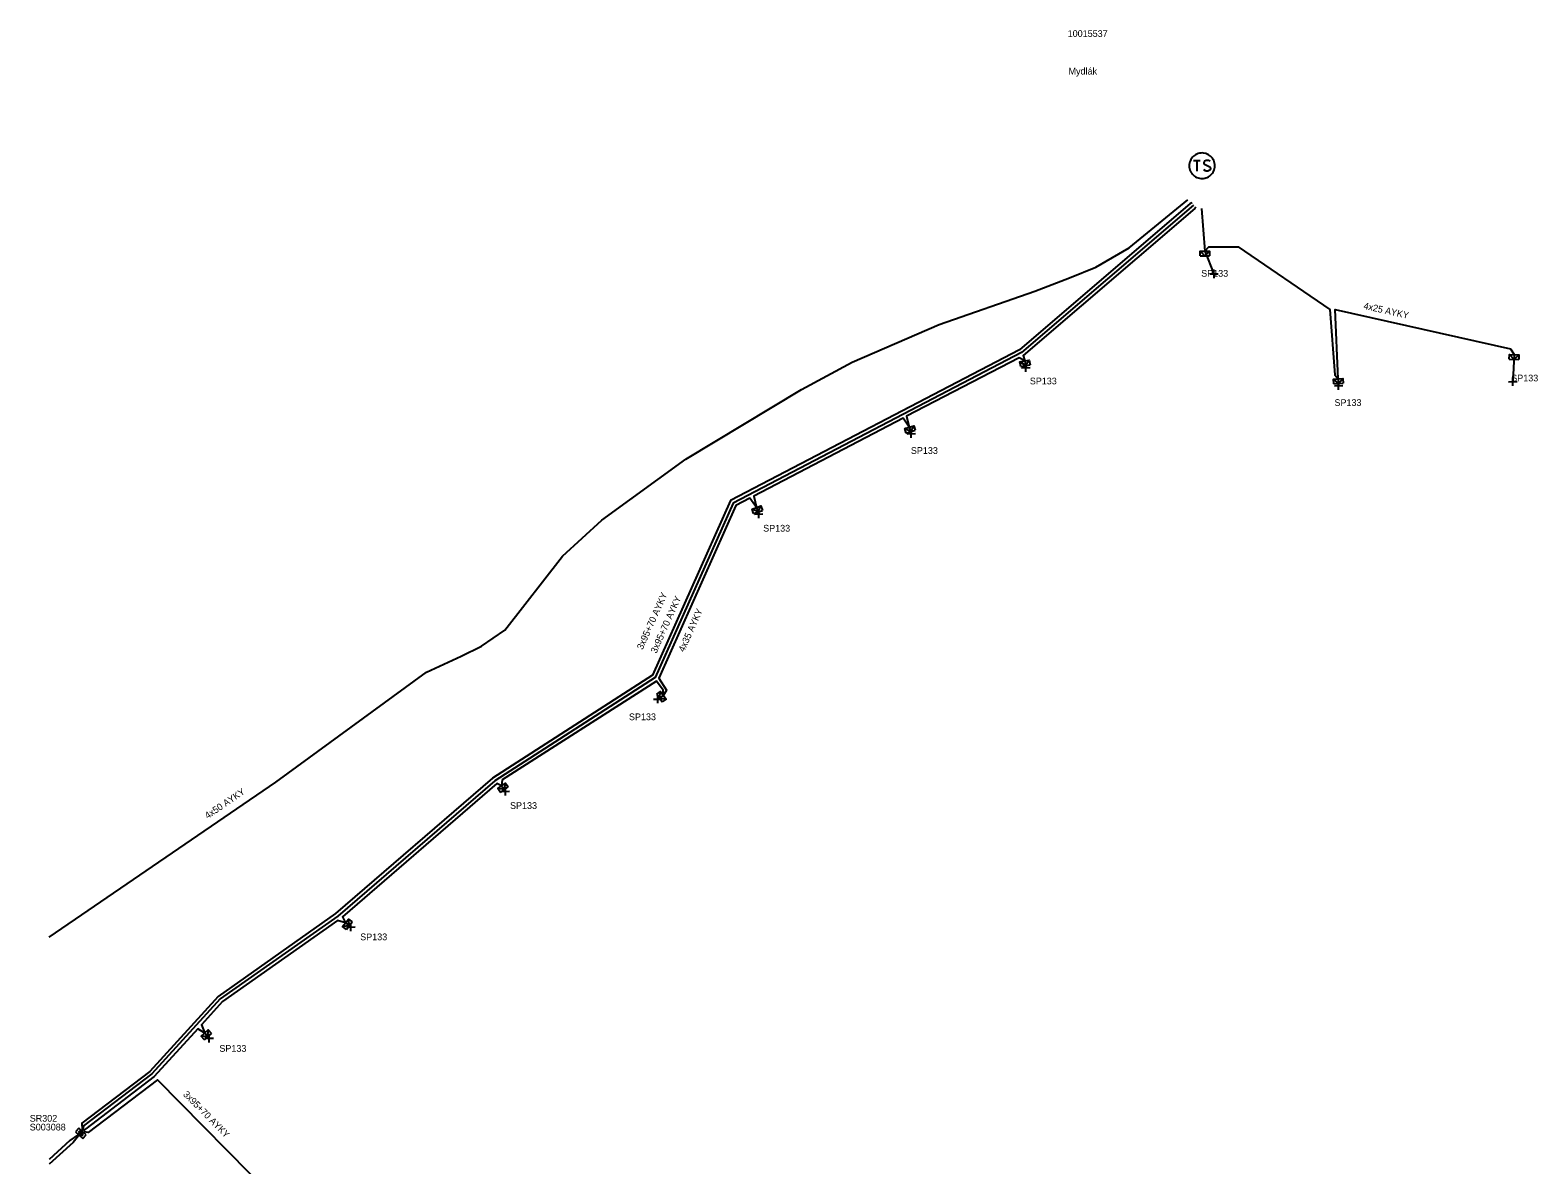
# Model space of a CAD drawing. Extents: x -762503 to -762212, y -1153994 to -1153331.
# Drawn here: x -762502.8 to -762279.8, y -1153498.9 to -1153331.1 of the extents above; entities that cross this region are included whole.
import ezdxf

# ---------------------------------------------------------------- set-up
doc = ezdxf.new("R2010")
doc.units = 0
for name, color, linetype in [('Vrstva 25', 7, 'Continuous'), ('Vrstva 26', 7, 'Continuous'), ('Vrstva 27', 7, 'Continuous'), ('Vrstva 28', 7, 'Continuous'), ('Vrstva 29', 7, 'Continuous'), ('Vrstva 30', 7, 'Continuous'), ('Vrstva 31', 7, 'Continuous'), ('Vrstva 33', 7, 'Continuous'), ('Vrstva 34', 7, 'Continuous'), ('Vrstva 5', 7, 'Continuous'), ('Vrstva 59', 7, 'Continuous'), ('Vrstva 6', 7, 'Continuous')]:
    doc.layers.add(name, color=color, linetype=linetype)

msp = doc.modelspace()

# ---------------------------------------------------------------- linework, layer by layer
at = {"layer": 'Vrstva 25'}
for points in [[(-762327.567, -1153351.151), (-762327.578, -1153350.954), (-762327.609, -1153350.758), (-762327.66, -1153350.567), (-762327.732, -1153350.382), (-762327.821, -1153350.207), (-762327.929, -1153350.041), (-762328.053, -1153349.887), (-762328.193, -1153349.747), (-762328.347, -1153349.623), (-762328.513, -1153349.515), (-762328.689, -1153349.425), (-762328.873, -1153349.354), (-762329.26, -1153349.272), (-762329.26, -1153349.272), (-762329.457, -1153349.261), (-762329.655, -1153349.272), (-762329.851, -1153349.303), (-762330.041, -1153349.354), (-762330.227, -1153349.425), (-762330.402, -1153349.515), (-762330.568, -1153349.623), (-762330.722, -1153349.747), (-762330.862, -1153349.887), (-762330.986, -1153350.041), (-762331.094, -1153350.207), (-762331.184, -1153350.382), (-762331.255, -1153350.567), (-762331.306, -1153350.758), (-762331.337, -1153350.954), (-762331.348, -1153351.151), (-762331.337, -1153351.349), (-762331.306, -1153351.545), (-762331.255, -1153351.735), (-762331.184, -1153351.92), (-762331.094, -1153352.096), (-762330.986, -1153352.262), (-762330.861, -1153352.416), (-762330.722, -1153352.555), (-762330.568, -1153352.68), (-762330.402, -1153352.788), (-762330.226, -1153352.878), (-762330.041, -1153352.949), (-762329.851, -1153353), (-762329.655, -1153353.031), (-762329.457, -1153353.042), (-762329.26, -1153353.031), (-762329.065, -1153353), (-762328.873, -1153352.949), (-762328.689, -1153352.878), (-762328.513, -1153352.788), (-762328.347, -1153352.68), (-762328.193, -1153352.555), (-762328.053, -1153352.416), (-762327.929, -1153352.262), (-762327.821, -1153352.096), (-762327.732, -1153351.92), (-762327.66, -1153351.735), (-762327.609, -1153351.545), (-762327.578, -1153351.349), (-762327.567, -1153351.151)], [(-762330.719, -1153350.368), (-762329.711, -1153350.368)], [(-762330.215, -1153350.368), (-762330.215, -1153351.942)], [(-762328.262, -1153350.494), (-762328.514, -1153350.368), (-762328.829, -1153350.368), (-762329.081, -1153350.494), (-762329.207, -1153350.682), (-762329.207, -1153350.746), (-762329.081, -1153350.934), (-762328.325, -1153351.312), (-762328.199, -1153351.47), (-762328.199, -1153351.628), (-762328.325, -1153351.816), (-762328.577, -1153351.942), (-762328.829, -1153351.942), (-762328.955, -1153351.88), (-762329.207, -1153351.754)]]:
    msp.add_lwpolyline(points, dxfattribs=at)
at = {"layer": 'Vrstva 28'}
for points in [[(-762495.603, -1153493.457), (-762496.105, -1153494.014)], [(-762496.105, -1153494.014), (-762494.991, -1153495.018)], [(-762495.449, -1153493.842), (-762495.702, -1153494.123)], [(-762495.702, -1153494.123), (-762495.149, -1153494.621)], [(-762495.446, -1153493.909), (-762495.636, -1153494.119)], [(-762495.636, -1153494.119), (-762495.153, -1153494.554)], [(-762494.489, -1153494.461), (-762495.603, -1153493.457)], [(-762495.442, -1153493.976), (-762495.569, -1153494.116)], [(-762495.569, -1153494.116), (-762495.156, -1153494.487)], [(-762495.439, -1153494.042), (-762495.502, -1153494.112)], [(-762495.502, -1153494.112), (-762495.16, -1153494.421)], [(-762494.896, -1153494.34), (-762495.449, -1153493.842)], [(-762494.963, -1153494.344), (-762495.446, -1153493.909)], [(-762495.03, -1153494.347), (-762495.442, -1153493.976)], [(-762495.44, -1153494.105), (-762495.159, -1153494.358)], [(-762495.097, -1153494.351), (-762495.439, -1153494.042)], [(-762495.16, -1153494.421), (-762495.097, -1153494.351)], [(-762495.156, -1153494.487), (-762495.03, -1153494.347)], [(-762495.153, -1153494.554), (-762494.963, -1153494.344)], [(-762495.149, -1153494.621), (-762494.896, -1153494.34)], [(-762494.991, -1153495.018), (-762494.489, -1153494.461)]]:
    msp.add_lwpolyline(points, dxfattribs=at)
at = {"layer": 'Vrstva 31'}
for points in [[(-762329.053, -1153364.48), (-762329.753, -1153363.78)], [(-762329.753, -1153364.48), (-762329.753, -1153363.78), (-762328.353, -1153363.78), (-762328.353, -1153364.48)], [(-762329.753, -1153364.48), (-762328.353, -1153364.48)], [(-762329.053, -1153364.48), (-762328.353, -1153363.78)], [(-762284.006, -1153379.755), (-762283.982, -1153379.056), (-762282.583, -1153379.105), (-762282.607, -1153379.804)], [(-762283.307, -1153379.78), (-762283.982, -1153379.056)], [(-762283.307, -1153379.78), (-762282.583, -1153379.105)], [(-762356.261, -1153380.821), (-762356.382, -1153380.132), (-762355.004, -1153379.889), (-762354.882, -1153380.578)], [(-762355.571, -1153380.7), (-762356.382, -1153380.132)], [(-762356.261, -1153380.821), (-762354.882, -1153380.578)], [(-762355.571, -1153380.7), (-762355.004, -1153379.889)], [(-762284.006, -1153379.755), (-762282.607, -1153379.804)], [(-762309.983, -1153383.418), (-762310.032, -1153382.719), (-762308.635, -1153382.622), (-762308.586, -1153383.32)], [(-762309.285, -1153383.369), (-762310.032, -1153382.719)], [(-762309.983, -1153383.418), (-762308.586, -1153383.32)], [(-762309.285, -1153383.369), (-762308.635, -1153382.622)], [(-762373.217, -1153390.685), (-762373.422, -1153390.016), (-762372.083, -1153389.607), (-762371.879, -1153390.276)], [(-762372.548, -1153390.481), (-762373.422, -1153390.016)], [(-762373.217, -1153390.685), (-762371.879, -1153390.276)], [(-762372.548, -1153390.481), (-762372.083, -1153389.607)], [(-762395.787, -1153402.581), (-762396.015, -1153401.92), (-762394.691, -1153401.464), (-762394.463, -1153402.126)], [(-762395.125, -1153402.354), (-762394.691, -1153401.464)], [(-762395.125, -1153402.354), (-762396.015, -1153401.92)], [(-762395.787, -1153402.581), (-762394.463, -1153402.126)], [(-762410.107, -1153429.276), (-762409.534, -1153428.874), (-762408.731, -1153430.021), (-762409.304, -1153430.422)], [(-762410.107, -1153429.276), (-762409.304, -1153430.422)], [(-762409.706, -1153429.849), (-762409.534, -1153428.874)], [(-762409.706, -1153429.849), (-762408.731, -1153430.021)], [(-762433.224, -1153443.817), (-762433.626, -1153443.244), (-762432.479, -1153442.441), (-762432.077, -1153443.014)], [(-762432.651, -1153443.415), (-762433.626, -1153443.244)], [(-762433.224, -1153443.817), (-762432.077, -1153443.014)], [(-762432.651, -1153443.415), (-762432.479, -1153442.441)], [(-762456.021, -1153464.085), (-762456.572, -1153463.654), (-762455.71, -1153462.551), (-762455.159, -1153462.982)], [(-762455.59, -1153463.533), (-762456.572, -1153463.654)], [(-762456.021, -1153464.085), (-762455.159, -1153462.982)], [(-762455.59, -1153463.533), (-762455.71, -1153462.551)], [(-762477.024, -1153480.411), (-762477.492, -1153479.89), (-762476.452, -1153478.954), (-762475.983, -1153479.474)], [(-762477.024, -1153480.411), (-762475.983, -1153479.474)], [(-762476.504, -1153479.942), (-762476.452, -1153478.954)], [(-762476.504, -1153479.942), (-762477.492, -1153479.89)]]:
    msp.add_lwpolyline(points, dxfattribs=at)
at = {"layer": 'Vrstva 34'}
for points in [[(-762328.315, -1153367.141), (-762327.065, -1153367.119)], [(-762327.679, -1153367.755), (-762327.701, -1153366.505)], [(-762356.145, -1153381.011), (-762354.895, -1153380.989)], [(-762355.509, -1153381.625), (-762355.531, -1153380.375)], [(-762309.885, -1153383.681), (-762308.635, -1153383.659)], [(-762309.249, -1153384.295), (-762309.271, -1153383.045)], [(-762284.105, -1153383.091), (-762282.855, -1153383.069)], [(-762283.469, -1153383.705), (-762283.491, -1153382.455)], [(-762372.459, -1153391.395), (-762372.481, -1153390.145)], [(-762373.095, -1153390.781), (-762371.845, -1153390.759)], [(-762395.655, -1153402.651), (-762394.405, -1153402.629)], [(-762395.019, -1153403.265), (-762395.041, -1153402.015)], [(-762410.575, -1153430.031), (-762409.325, -1153430.009)], [(-762409.939, -1153430.645), (-762409.961, -1153429.395)], [(-762433.115, -1153443.671), (-762431.865, -1153443.649)], [(-762432.479, -1153444.285), (-762432.501, -1153443.035)], [(-762455.975, -1153463.731), (-762454.725, -1153463.709)], [(-762455.339, -1153464.345), (-762455.361, -1153463.095)], [(-762476.299, -1153480.795), (-762476.321, -1153479.545)], [(-762476.935, -1153480.181), (-762475.685, -1153480.159)]]:
    msp.add_lwpolyline(points, dxfattribs=at)
at = {"layer": 'Vrstva 5'}
for points in [[(-762500, -1153465.22), (-762466.43, -1153442.33), (-762444.16, -1153426.04), (-762439.02, -1153423.69), (-762436.02, -1153422.19), (-762432.59, -1153419.83), (-762424.03, -1153408.9), (-762418.24, -1153403.54), (-762405.82, -1153394.54), (-762388.69, -1153384.25), (-762381.19, -1153380.18), (-762368.34, -1153374.61), (-762354.2, -1153369.68), (-762349.06, -1153367.75), (-762345.18, -1153366.14), (-762340.25, -1153363.3), (-762331.58, -1153356.18)], [(-762330.94, -1153356.62), (-762331.2, -1153356.74), (-762356.46, -1153378.36), (-762399.19, -1153400.67), (-762410.72, -1153426.5), (-762434.38, -1153441.69), (-762457.61, -1153461.74), (-762475, -1153473.99), (-762485.11, -1153485.08), (-762495.16, -1153492.75), (-762495.11, -1153493.74)], [(-762330.72, -1153356.97), (-762356.18, -1153378.77), (-762398.8, -1153401.03), (-762410.33, -1153426.84), (-762434.08, -1153442.09), (-762457.3, -1153462.13), (-762474.67, -1153474.37), (-762484.77, -1153485.45), (-762494.9, -1153493.13), (-762495.01, -1153493.82)], [(-762330.37, -1153357.26), (-762330.5, -1153357.47), (-762355.89, -1153379.19), (-762355.69, -1153380.01), (-762356.51, -1153379.57), (-762373.15, -1153388.19), (-762372.75, -1153389.81), (-762373.66, -1153388.46), (-762395.75, -1153400.01), (-762395.35, -1153401.69), (-762396.35, -1153400.3), (-762398.42, -1153401.4), (-762409.82, -1153426.93), (-762408.69, -1153428.68), (-762409.13, -1153429.45), (-762409.17, -1153428.7), (-762410.15, -1153427.35), (-762432.97, -1153441.98), (-762433.06, -1153442.84), (-762433.77, -1153442.51), (-762456.57, -1153462.2), (-762456.14, -1153463.1), (-762457.32, -1153462.78), (-762474.34, -1153474.75), (-762477.47, -1153478.21), (-762476.97, -1153479.42), (-762477.98, -1153478.78), (-762484.43, -1153485.83), (-762494.55, -1153493.57), (-762494.92, -1153493.91)], [(-762329.56, -1153357.45), (-762329.05, -1153363.78), (-762328.43, -1153363.12), (-762324.09, -1153363.12), (-762310.53, -1153372.39), (-762309.82, -1153382.07), (-762309.33, -1153382.67), (-762309.78, -1153372.39), (-762283.81, -1153378.24), (-762283.28, -1153379.08)], [(-762466.85, -1153503.67), (-762483.97, -1153486.34), (-762494.21, -1153494.09), (-762494.82, -1153494)], [(-762495.78, -1153494.49), (-762496.92, -1153495.32), (-762500, -1153498.1)], [(-762495.62, -1153494.63), (-762496.45, -1153495.59), (-762500, -1153498.8)]]:
    msp.add_lwpolyline(points, dxfattribs=at)
at = {"layer": 'Vrstva 59'}
for points in [[(-762329.05, -1153363.78), (-762327.69, -1153367.13)], [(-762283.28, -1153379.08), (-762283.48, -1153383.08)], [(-762355.69, -1153380.01), (-762355.52, -1153381)], [(-762309.33, -1153382.67), (-762309.26, -1153383.67)], [(-762372.75, -1153389.81), (-762372.47, -1153390.77)], [(-762395.35, -1153401.69), (-762395.03, -1153402.64)], [(-762409.13, -1153429.45), (-762409.95, -1153430.02)], [(-762433.06, -1153442.84), (-762432.49, -1153443.66)], [(-762456.14, -1153463.1), (-762455.35, -1153463.72)], [(-762476.97, -1153479.42), (-762476.31, -1153480.17)]]:
    msp.add_lwpolyline(points, dxfattribs=at)

# ---------------------------------------------------------------- texts
at = {"layer": 'Vrstva 26'}
msp.add_text('10015537', height=0.9943, dxfattribs=at).set_placement((-762349.33, -1153332.11))
at = {"layer": 'Vrstva 27'}
msp.add_text('Mydlák', height=0.9943, dxfattribs=at).set_placement((-762349.2, -1153337.66))
at = {"layer": 'Vrstva 29'}
msp.add_text('S003088', height=0.9943, dxfattribs=at).set_placement((-762502.85, -1153493.81))
at = {"layer": 'Vrstva 30'}
msp.add_text('SR302', height=0.9943, dxfattribs=at).set_placement((-762502.85, -1153492.51))
at = {"layer": 'Vrstva 33'}
for p in [(-762329.58, -1153367.56), (-762354.93, -1153383.48), (-762283.72, -1153383.04), (-762309.87, -1153386.67), (-762372.52, -1153393.76), (-762394.37, -1153405.25), (-762414.22, -1153433.14), (-762431.81, -1153446.26), (-762453.97, -1153465.68), (-762474.8, -1153482.18)]:
    msp.add_text('SP133', height=0.9943, dxfattribs=at).set_placement(p)
at = {"layer": 'Vrstva 6'}
for s, height, rotation, p in [('4x25 AYKY', 0.9943, 347.29793, (-762305.63, -1153372.3)), ('3x95+70 AYKY', 0.99429, 65.93911, (-762412.2, -1153422.8)), ('3x95+70 AYKY', 0.99429, 65.93911, (-762410.16, -1153423.34)), ('4x35 AYKY', 0.9943, 65.9439, (-762406.06, -1153423.13)), ('4x50 AYKY', 0.9943, 34.29276, (-762476.54, -1153447.78)), ('3x95+70 AYKY', 0.99428, 314.6542, (-762480.25, -1153488.55))]:
    msp.add_text(s, height=height, rotation=rotation, dxfattribs=at).set_placement(p)

doc.saveas('drawing.dxf')
